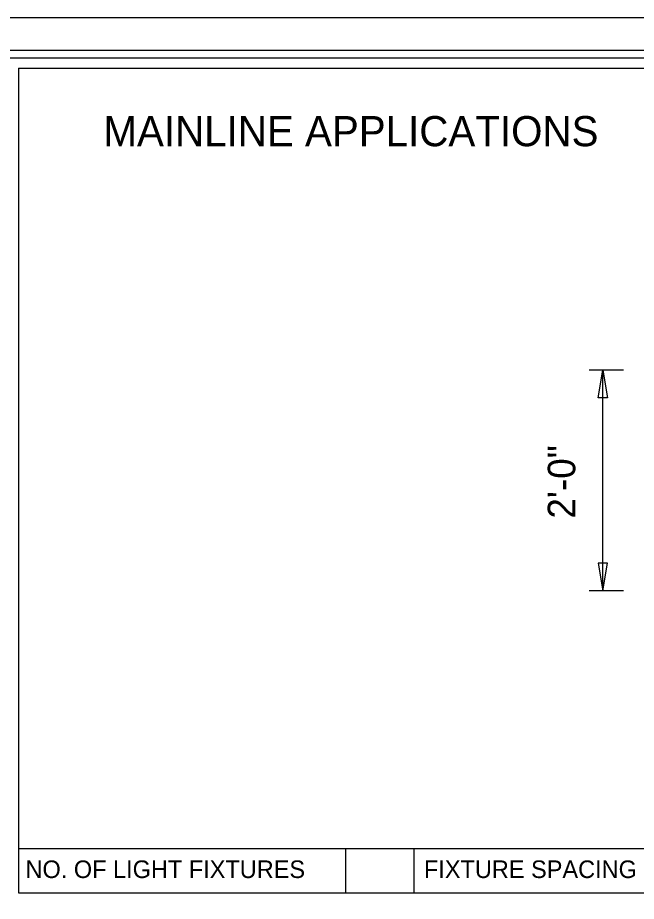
# Model space of a CAD drawing. Extents: x 17890587 to 17890754, y 17897693 to 17897992.
# Drawn here: x 17890595.51 to 17890601.12, y 17897896.19 to 17897904.2 of the extents above; entities that cross this region are included whole.
import ezdxf

# ---------------------------------------------------------------- set-up
doc = ezdxf.new("R2010")
doc.units = 0
for name, color, linetype in [('GSDims', 7, 'Continuous'), ('PlotBorder_dp', 7, 'Continuous'), ('SheetBorder_dp', 7, 'Continuous'), ('SheetLinesMisc2_dp', 7, 'Continuous'), ('TextMinor', 7, 'Continuous'), ('TextMisc', 7, 'Continuous')]:
    doc.layers.add(name, color=color, linetype=linetype)

msp = doc.modelspace()

# ---------------------------------------------------------------- linework, layer by layer
at = {"layer": 'GSDims'}
for p, q in [((17890601.0037, 17897901.0074), (17890600.6912, 17897901.0074)), ((17890600.8162, 17897899.0074), (17890600.8162, 17897901.0074)), ((17890601.0037, 17897899.0074), (17890600.6912, 17897899.0074))]:
    msp.add_line(p, q, dxfattribs=at)
for points in [[(17890600.8162, 17897901.0074), (17890600.8579, 17897900.7574), (17890600.7745, 17897900.7574)], [(17890600.8162, 17897899.0074), (17890600.8579, 17897899.2574), (17890600.7745, 17897899.2574)]]:
    msp.add_lwpolyline(points, close=True, dxfattribs=at)
at = {"layer": 'PlotBorder_dp'}
msp.add_lwpolyline([(17890586.7562, 17897873.1039), (17890635.165, 17897873.1039), (17890635.165, 17897904.2029), (17890586.7562, 17897904.2029)], close=True, dxfattribs=at)
at = {"layer": 'SheetBorder_dp'}
msp.add_line((17890588.3699, 17897903.9095), (17890633.5514, 17897903.9095), dxfattribs=at)
at = {"layer": 'SheetLinesMisc2_dp'}
for p, q in [((17890588.4536, 17897903.8393), (17890611.0193, 17897903.8393)), ((17890595.5165, 17897903.7458), (17890610.866, 17897903.7458)), ((17890595.5165, 17897903.7458), (17890595.5165, 17897896.2689)), ((17890595.5165, 17897896.6696), (17890610.866, 17897896.6696)), ((17890598.4813, 17897896.6696), (17890598.4813, 17897896.2689)), ((17890599.1025, 17897896.6696), (17890599.1025, 17897896.2689)), ((17890595.5165, 17897896.2689), (17890610.866, 17897896.2689))]:
    msp.add_line(p, q, dxfattribs=at)

# ---------------------------------------------------------------- texts
at = {"layer": 'GSDims'}
msp.add_text('2\'-0"', height=0.25, rotation=90, dxfattribs=at).set_placement((17890600.5662, 17897899.6614))
at = {"layer": 'TextMinor'}
for s, p in [('NO. OF LIGHT FIXTURES', (17890595.5811, 17897896.4031)), ('FIXTURE SPACING', (17890599.1937, 17897896.4031))]:
    msp.add_text(s, height=0.159436, dxfattribs=at).set_placement(p)
at = {"layer": 'TextMisc'}
msp.add_text('MAINLINE APPLICATIONS', height=0.273336, dxfattribs=at).set_placement((17890596.2874, 17897903.0376))

doc.saveas('drawing.dxf')
